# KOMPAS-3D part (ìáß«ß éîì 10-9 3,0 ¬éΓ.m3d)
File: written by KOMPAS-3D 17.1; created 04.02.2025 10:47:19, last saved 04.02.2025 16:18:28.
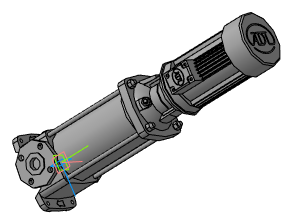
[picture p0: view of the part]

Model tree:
1. Операция без истории:1  (labels: Насос ВМН 10-9 3,0 кВт)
